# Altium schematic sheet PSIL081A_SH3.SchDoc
size 558 x 431 mm; Date: Not shown in title block; ApprovedBy: Not shown in title block; CheckedBy: Not shown in title block; Author: Not shown in title block; CompanyName: Not shown in title block; Engineer: Not shown in title block; Organization: Not shown in title block; Address1: Not shown in title block; Address2: Not shown in title block; Address3: Not shown in title block; Address4: Not shown in title block; DocumentNumber: 3; Revision: Use project parameter SCH_Rev; SheetNumber: 3; SheetTotal: 5; PageSetup: Record=PageOptions¦CenterHorizontal=True¦CenterVertical=True¦PrintScale=1.00¦XCorrection=1.00¦YCorrection=1.00¦PrintKind=0¦BorderSize=5000000¦LeftOffset=0¦BottomOffset=0¦Orientation=2¦PaperLength=1000¦PaperWidth=1000¦Scale=100¦PaperSource=15¦PrintQuality=600¦MediaType=1¦DitherType=10¦PaperKind=Letter¦PrintScaleMode=1
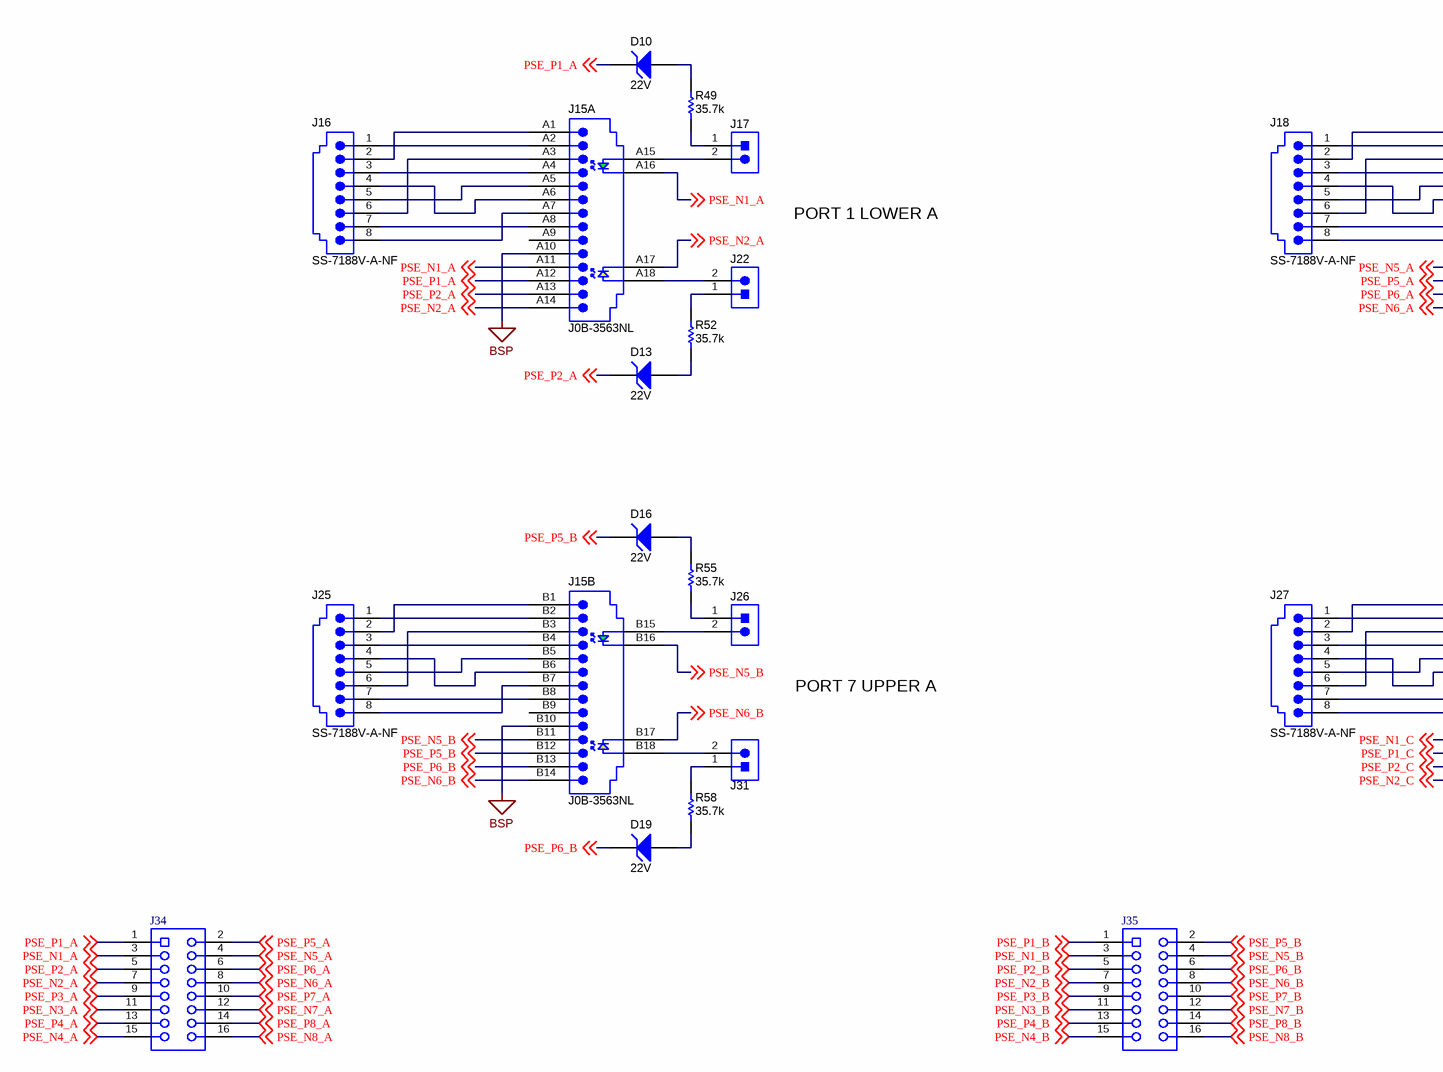
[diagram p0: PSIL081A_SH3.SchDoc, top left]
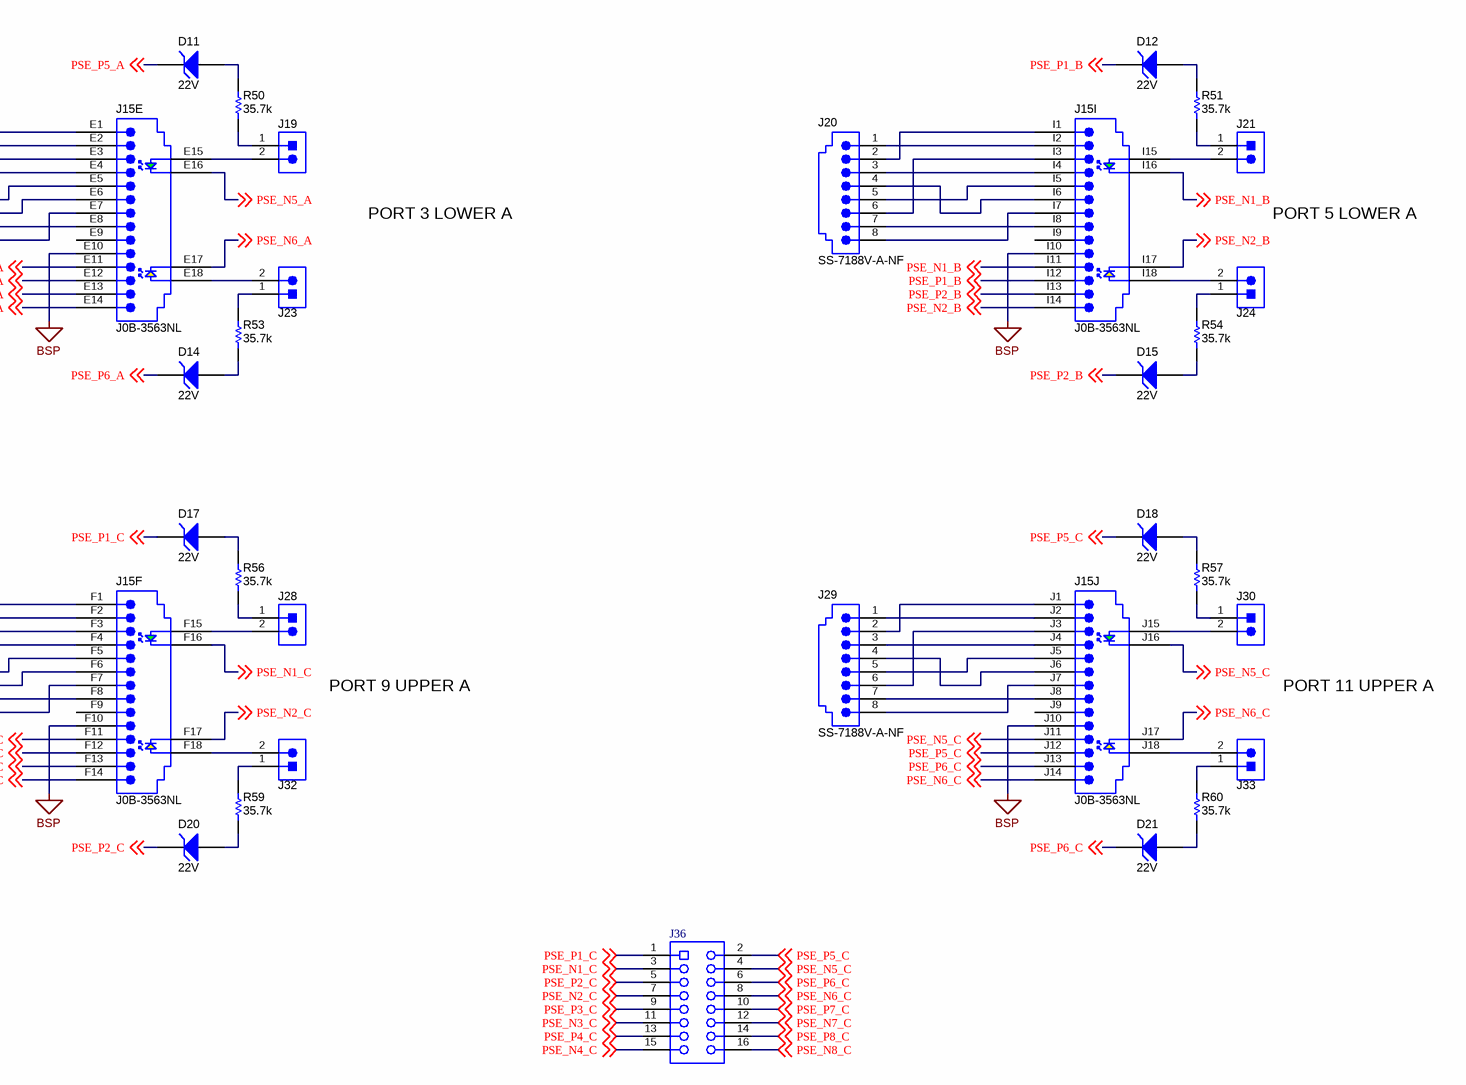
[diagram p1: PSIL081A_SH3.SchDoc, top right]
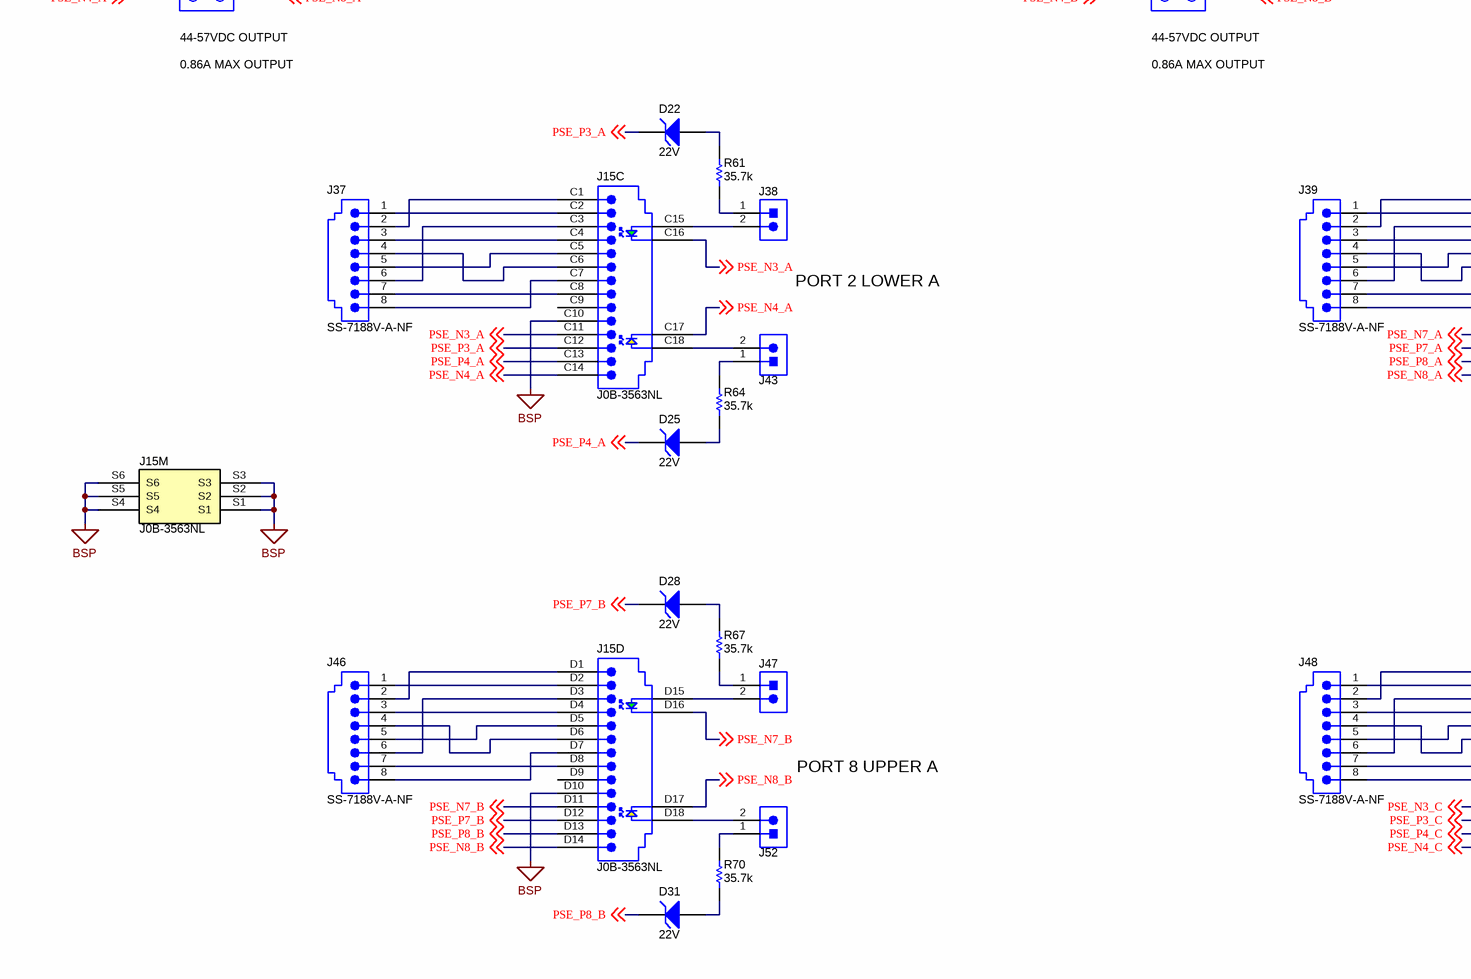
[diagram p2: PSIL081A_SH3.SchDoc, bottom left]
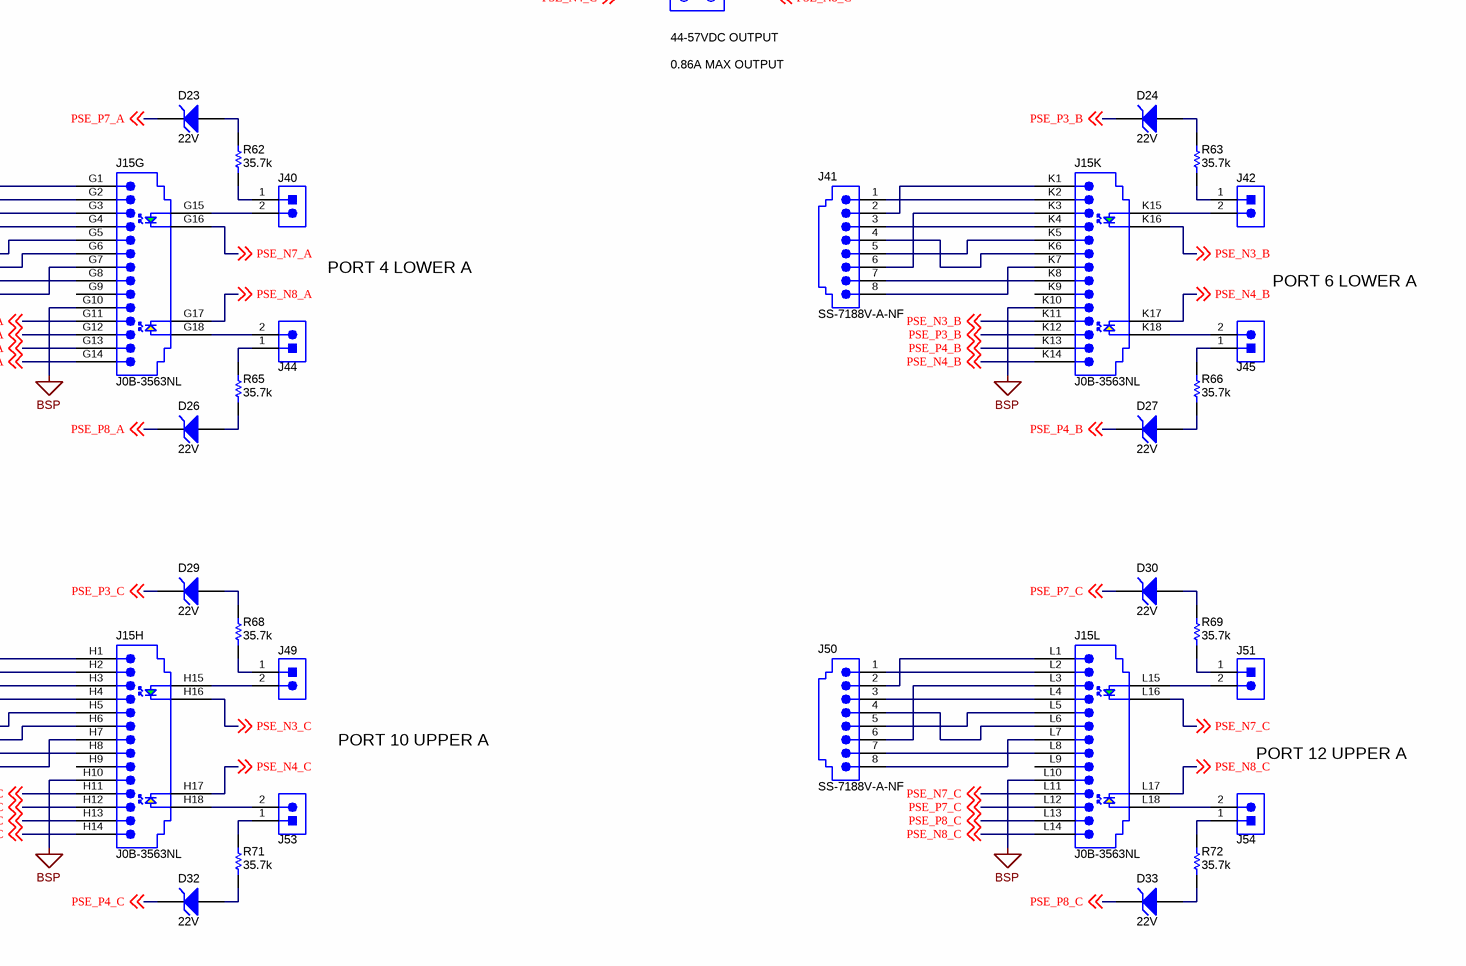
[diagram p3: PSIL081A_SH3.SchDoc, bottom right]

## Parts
D10  Vz_V: 22V  [SOD-123]  (hidden comment: MMSZ5251B-7-F)
D11  Vz_V: 22V  [SOD-123]  (hidden comment: MMSZ5251B-7-F)
D12  Vz_V: 22V  [SOD-123]  (hidden comment: MMSZ5251B-7-F)
D13  Vz_V: 22V  [SOD-123]  (hidden comment: MMSZ5251B-7-F)
D14  Vz_V: 22V  [SOD-123]  (hidden comment: MMSZ5251B-7-F)
D15  Vz_V: 22V  [SOD-123]  (hidden comment: MMSZ5251B-7-F)
D16  Vz_V: 22V  [SOD-123]  (hidden comment: MMSZ5251B-7-F)
D17  Vz_V: 22V  [SOD-123]  (hidden comment: MMSZ5251B-7-F)
D18  Vz_V: 22V  [SOD-123]  (hidden comment: MMSZ5251B-7-F)
D19  Vz_V: 22V  [SOD-123]  (hidden comment: MMSZ5251B-7-F)
D20  Vz_V: 22V  [SOD-123]  (hidden comment: MMSZ5251B-7-F)
D21  Vz_V: 22V  [SOD-123]  (hidden comment: MMSZ5251B-7-F)
D22  Vz_V: 22V  [SOD-123]  (hidden comment: MMSZ5251B-7-F)
D23  Vz_V: 22V  [SOD-123]  (hidden comment: MMSZ5251B-7-F)
D24  Vz_V: 22V  [SOD-123]  (hidden comment: MMSZ5251B-7-F)
D25  Vz_V: 22V  [SOD-123]  (hidden comment: MMSZ5251B-7-F)
D26  Vz_V: 22V  [SOD-123]  (hidden comment: MMSZ5251B-7-F)
D27  Vz_V: 22V  [SOD-123]  (hidden comment: MMSZ5251B-7-F)
D28  Vz_V: 22V  [SOD-123]  (hidden comment: MMSZ5251B-7-F)
D29  Vz_V: 22V  [SOD-123]  (hidden comment: MMSZ5251B-7-F)
D30  Vz_V: 22V  [SOD-123]  (hidden comment: MMSZ5251B-7-F)
D31  Vz_V: 22V  [SOD-123]  (hidden comment: MMSZ5251B-7-F)
D32  Vz_V: 22V  [SOD-123]  (hidden comment: MMSZ5251B-7-F)
D33  Vz_V: 22V  [SOD-123]  (hidden comment: MMSZ5251B-7-F)
J15  J0B-3563NL  [Pulse_J0B-3563NL]  (parts A,B,C,D,E,F,G,H,I,J,K,L,M of 13)
J16  SS-7188V-A-NF  [CONN_SS-7188V-A-NF]
J17  TSW-102-07-G-S  [TSW-102-07-G-S]  (value not drawn)
J18  SS-7188V-A-NF  [CONN_SS-7188V-A-NF]
J19  TSW-102-07-G-S  [TSW-102-07-G-S]  (value not drawn)
J20  SS-7188V-A-NF  [CONN_SS-7188V-A-NF]
J21  TSW-102-07-G-S  [TSW-102-07-G-S]  (value not drawn)
J22  TSW-102-07-G-S  [TSW-102-07-G-S]  (value not drawn)
J23  TSW-102-07-G-S  [TSW-102-07-G-S]  (value not drawn)
J24  TSW-102-07-G-S  [TSW-102-07-G-S]  (value not drawn)
J25  SS-7188V-A-NF  [CONN_SS-7188V-A-NF]
J26  TSW-102-07-G-S  [TSW-102-07-G-S]  (value not drawn)
J27  SS-7188V-A-NF  [CONN_SS-7188V-A-NF]
J28  TSW-102-07-G-S  [TSW-102-07-G-S]  (value not drawn)
J29  SS-7188V-A-NF  [CONN_SS-7188V-A-NF]
J30  TSW-102-07-G-S  [TSW-102-07-G-S]  (value not drawn)
J31  TSW-102-07-G-S  [TSW-102-07-G-S]  (value not drawn)
J32  TSW-102-07-G-S  [TSW-102-07-G-S]  (value not drawn)
J33  TSW-102-07-G-S  [TSW-102-07-G-S]  (value not drawn)
J34  SSW-108-21-G-D  [Samtec_SSW-108-01-x-D]  (value not drawn)
J35  SSW-108-21-G-D  [Samtec_SSW-108-01-x-D]  (value not drawn)
J36  SSW-108-21-G-D  [Samtec_SSW-108-01-x-D]  (value not drawn)
J37  SS-7188V-A-NF  [CONN_SS-7188V-A-NF]
J38  TSW-102-07-G-S  [TSW-102-07-G-S]  (value not drawn)
J39  SS-7188V-A-NF  [CONN_SS-7188V-A-NF]
J40  TSW-102-07-G-S  [TSW-102-07-G-S]  (value not drawn)
J41  SS-7188V-A-NF  [CONN_SS-7188V-A-NF]
J42  TSW-102-07-G-S  [TSW-102-07-G-S]  (value not drawn)
J43  TSW-102-07-G-S  [TSW-102-07-G-S]  (value not drawn)
J44  TSW-102-07-G-S  [TSW-102-07-G-S]  (value not drawn)
J45  TSW-102-07-G-S  [TSW-102-07-G-S]  (value not drawn)
J46  SS-7188V-A-NF  [CONN_SS-7188V-A-NF]
J47  TSW-102-07-G-S  [TSW-102-07-G-S]  (value not drawn)
J48  SS-7188V-A-NF  [CONN_SS-7188V-A-NF]
J49  TSW-102-07-G-S  [TSW-102-07-G-S]  (value not drawn)
J50  SS-7188V-A-NF  [CONN_SS-7188V-A-NF]
J51  TSW-102-07-G-S  [TSW-102-07-G-S]  (value not drawn)
J52  TSW-102-07-G-S  [TSW-102-07-G-S]  (value not drawn)
J53  TSW-102-07-G-S  [TSW-102-07-G-S]  (value not drawn)
J54  TSW-102-07-G-S  [TSW-102-07-G-S]  (value not drawn)
R49  ValueDisplayed: 35.7k  [0603]  (hidden comment: CRCW060335K7FKEA)
R50  ValueDisplayed: 35.7k  [0603]  (hidden comment: CRCW060335K7FKEA)
R51  ValueDisplayed: 35.7k  [0603]  (hidden comment: CRCW060335K7FKEA)
R52  ValueDisplayed: 35.7k  [0603]  (hidden comment: CRCW060335K7FKEA)
R53  ValueDisplayed: 35.7k  [0603]  (hidden comment: CRCW060335K7FKEA)
R54  ValueDisplayed: 35.7k  [0603]  (hidden comment: CRCW060335K7FKEA)
R55  ValueDisplayed: 35.7k  [0603]  (hidden comment: CRCW060335K7FKEA)
R56  ValueDisplayed: 35.7k  [0603]  (hidden comment: CRCW060335K7FKEA)
R57  ValueDisplayed: 35.7k  [0603]  (hidden comment: CRCW060335K7FKEA)
R58  ValueDisplayed: 35.7k  [0603]  (hidden comment: CRCW060335K7FKEA)
R59  ValueDisplayed: 35.7k  [0603]  (hidden comment: CRCW060335K7FKEA)
R60  ValueDisplayed: 35.7k  [0603]  (hidden comment: CRCW060335K7FKEA)
R61  ValueDisplayed: 35.7k  [0603]  (hidden comment: CRCW060335K7FKEA)
R62  ValueDisplayed: 35.7k  [0603]  (hidden comment: CRCW060335K7FKEA)
R63  ValueDisplayed: 35.7k  [0603]  (hidden comment: CRCW060335K7FKEA)
R64  ValueDisplayed: 35.7k  [0603]  (hidden comment: CRCW060335K7FKEA)
R65  ValueDisplayed: 35.7k  [0603]  (hidden comment: CRCW060335K7FKEA)
R66  ValueDisplayed: 35.7k  [0603]  (hidden comment: CRCW060335K7FKEA)
R67  ValueDisplayed: 35.7k  [0603]  (hidden comment: CRCW060335K7FKEA)
R68  ValueDisplayed: 35.7k  [0603]  (hidden comment: CRCW060335K7FKEA)
R69  ValueDisplayed: 35.7k  [0603]  (hidden comment: CRCW060335K7FKEA)
R70  ValueDisplayed: 35.7k  [0603]  (hidden comment: CRCW060335K7FKEA)
R71  ValueDisplayed: 35.7k  [0603]  (hidden comment: CRCW060335K7FKEA)
R72  ValueDisplayed: 35.7k  [0603]  (hidden comment: CRCW060335K7FKEA)

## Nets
BSP: J15.A10 J15.B10 J15.C10 J15.D10 J15.E10 J15.F10 J15.G10 J15.H10 J15.I10 J15.J10 J15.K10 J15.L10 J15.S1 J15.S2 J15.S3 J15.S4 J15.S5 J15.S6
PSE_N1_A: J15.A11 J15.A16 J34.3 ; off-sheet PSE_N1_A
PSE_N1_B: J15.I11 J15.I16 J35.3 ; off-sheet PSE_N1_B
PSE_N1_C: J15.F11 J15.F16 J36.3 ; off-sheet PSE_N1_C
PSE_N2_A: J15.A14 J15.A17 J34.7 ; off-sheet PSE_N2_A
PSE_N2_B: J15.I14 J15.I17 J35.7 ; off-sheet PSE_N2_B
PSE_N2_C: J15.F14 J15.F17 J36.7 ; off-sheet PSE_N2_C
PSE_N3_A: J15.C11 J15.C16 J34.11 ; off-sheet PSE_N3_A
PSE_N3_B: J15.K11 J15.K16 J35.11 ; off-sheet PSE_N3_B
PSE_N3_C: J15.H11 J15.H16 J36.11 ; off-sheet PSE_N3_C
PSE_N4_A: J15.C14 J15.C17 J34.15 ; off-sheet PSE_N4_A
PSE_N4_B: J15.K14 J15.K17 J35.15 ; off-sheet PSE_N4_B
PSE_N4_C: J15.H14 J15.H17 J36.15 ; off-sheet PSE_N4_C
PSE_N5_A: J15.E11 J15.E16 J34.4 ; off-sheet PSE_N5_A
PSE_N5_B: J15.B11 J15.B16 J35.4 ; off-sheet PSE_N5_B
PSE_N5_C: J15.J11 J15.J16 J36.4 ; off-sheet PSE_N5_C
PSE_N6_A: J15.E14 J15.E17 J34.8 ; off-sheet PSE_N6_A
PSE_N6_B: J15.B14 J15.B17 J35.8 ; off-sheet PSE_N6_B
PSE_N6_C: J15.J14 J15.J17 J36.8 ; off-sheet PSE_N6_C
PSE_N7_A: J15.G11 J15.G16 J34.12 ; off-sheet PSE_N7_A
PSE_N7_B: J15.D11 J15.D16 J35.12 ; off-sheet PSE_N7_B
PSE_N7_C: J15.L11 J15.L16 J36.12 ; off-sheet PSE_N7_C
PSE_N8_A: J15.G14 J15.G17 J34.16 ; off-sheet PSE_N8_A
PSE_N8_B: J15.D14 J15.D17 J35.16 ; off-sheet PSE_N8_B
PSE_N8_C: J15.L14 J15.L17 J36.16 ; off-sheet PSE_N8_C
PSE_P1_A: D10.1(K) J15.A12 J34.1 ; off-sheet PSE_P1_A
PSE_P1_B: D12.1(K) J15.I12 J35.1 ; off-sheet PSE_P1_B
PSE_P1_C: D17.1(K) J15.F12 J36.1 ; off-sheet PSE_P1_C
PSE_P2_A: D13.1(K) J15.A13 J34.5 ; off-sheet PSE_P2_A
PSE_P2_B: D15.1(K) J15.I13 J35.5 ; off-sheet PSE_P2_B
PSE_P2_C: D20.1(K) J15.F13 J36.5 ; off-sheet PSE_P2_C
PSE_P3_A: D22.1(K) J15.C12 J34.9 ; off-sheet PSE_P3_A
PSE_P3_B: D24.1(K) J15.K12 J35.9 ; off-sheet PSE_P3_B
PSE_P3_C: D29.1(K) J15.H12 J36.9 ; off-sheet PSE_P3_C
PSE_P4_A: D25.1(K) J15.C13 J34.13 ; off-sheet PSE_P4_A
PSE_P4_B: D27.1(K) J15.K13 J35.13 ; off-sheet PSE_P4_B
PSE_P4_C: D32.1(K) J15.H13 J36.13 ; off-sheet PSE_P4_C
PSE_P5_A: D11.1(K) J15.E12 J34.2 ; off-sheet PSE_P5_A
PSE_P5_B: D16.1(K) J15.B12 J35.2 ; off-sheet PSE_P5_B
PSE_P5_C: D18.1(K) J15.J12 J36.2 ; off-sheet PSE_P5_C
PSE_P6_A: D14.1(K) J15.E13 J34.6 ; off-sheet PSE_P6_A
PSE_P6_B: D19.1(K) J15.B13 J35.6 ; off-sheet PSE_P6_B
PSE_P6_C: D21.1(K) J15.J13 J36.6 ; off-sheet PSE_P6_C
PSE_P7_A: D23.1(K) J15.G12 J34.10 ; off-sheet PSE_P7_A
PSE_P7_B: D28.1(K) J15.D12 J35.10 ; off-sheet PSE_P7_B
PSE_P7_C: D30.1(K) J15.L12 J36.10 ; off-sheet PSE_P7_C
PSE_P8_A: D26.1(K) J15.G13 J34.14 ; off-sheet PSE_P8_A
PSE_P8_B: D31.1(K) J15.D13 J35.14 ; off-sheet PSE_P8_B
PSE_P8_C: D33.1(K) J15.L13 J36.14 ; off-sheet PSE_P8_C
NetD10_2: D10.2(A) R49.1
NetD11_2: D11.2(A) R50.1
NetD12_2: D12.2(A) R51.1
NetD13_2: D13.2(A) R52.2
NetD14_2: D14.2(A) R53.2
NetD15_2: D15.2(A) R54.2
NetD16_2: D16.2(A) R55.1
NetD17_2: D17.2(A) R56.1
NetD18_2: D18.2(A) R57.1
NetD19_2: D19.2(A) R58.2
NetD20_2: D20.2(A) R59.2
NetD21_2: D21.2(A) R60.2
NetD22_2: D22.2(A) R61.1
NetD23_2: D23.2(A) R62.1
NetD24_2: D24.2(A) R63.1
NetD25_2: D25.2(A) R64.2
NetD26_2: D26.2(A) R65.2
NetD27_2: D27.2(A) R66.2
NetD28_2: D28.2(A) R67.1
NetD29_2: D29.2(A) R68.1
NetD30_2: D30.2(A) R69.1
NetD31_2: D31.2(A) R70.2
NetD32_2: D32.2(A) R71.2
NetD33_2: D33.2(A) R72.2
NetJ15_A1: J15.A1 J16.2
NetJ15_A2: J15.A2 J16.1
NetJ15_A3: J15.A3 J16.6
NetJ15_A4: J15.A4 J16.3
NetJ15_A5: J15.A5 J16.5
NetJ15_A6: J15.A6 J16.4
NetJ15_A7: J15.A7 J16.8
NetJ15_A8: J15.A8 J16.7
NetJ15_A15: J15.A15 J17.2
NetJ15_A18: J15.A18 J22.2
NetJ15_B1: J15.B1 J25.2
NetJ15_B2: J15.B2 J25.1
NetJ15_B3: J15.B3 J25.6
NetJ15_B4: J15.B4 J25.3
NetJ15_B5: J15.B5 J25.5
NetJ15_B6: J15.B6 J25.4
NetJ15_B7: J15.B7 J25.8
NetJ15_B8: J15.B8 J25.7
NetJ15_B15: J15.B15 J26.2
NetJ15_B18: J15.B18 J31.2
NetJ15_C1: J15.C1 J37.2
NetJ15_C2: J15.C2 J37.1
NetJ15_C3: J15.C3 J37.6
NetJ15_C4: J15.C4 J37.3
NetJ15_C5: J15.C5 J37.5
NetJ15_C6: J15.C6 J37.4
NetJ15_C7: J15.C7 J37.8
NetJ15_C8: J15.C8 J37.7
NetJ15_C15: J15.C15 J38.2
NetJ15_C18: J15.C18 J43.2
NetJ15_D1: J15.D1 J46.2
NetJ15_D2: J15.D2 J46.1
NetJ15_D3: J15.D3 J46.6
NetJ15_D4: J15.D4 J46.3
NetJ15_D5: J15.D5 J46.5
NetJ15_D6: J15.D6 J46.4
NetJ15_D7: J15.D7 J46.8
NetJ15_D8: J15.D8 J46.7
NetJ15_D15: J15.D15 J47.2
NetJ15_D18: J15.D18 J52.2
NetJ15_E1: J15.E1 J18.2
NetJ15_E2: J15.E2 J18.1
NetJ15_E3: J15.E3 J18.6
NetJ15_E4: J15.E4 J18.3
NetJ15_E5: J15.E5 J18.5
NetJ15_E6: J15.E6 J18.4
NetJ15_E7: J15.E7 J18.8
NetJ15_E8: J15.E8 J18.7
NetJ15_E15: J15.E15 J19.2
NetJ15_E18: J15.E18 J23.2
NetJ15_F1: J15.F1 J27.2
NetJ15_F2: J15.F2 J27.1
NetJ15_F3: J15.F3 J27.6
NetJ15_F4: J15.F4 J27.3
NetJ15_F5: J15.F5 J27.5
NetJ15_F6: J15.F6 J27.4
NetJ15_F7: J15.F7 J27.8
NetJ15_F8: J15.F8 J27.7
NetJ15_F15: J15.F15 J28.2
NetJ15_F18: J15.F18 J32.2
NetJ15_G1: J15.G1 J39.2
NetJ15_G2: J15.G2 J39.1
NetJ15_G3: J15.G3 J39.6
NetJ15_G4: J15.G4 J39.3
NetJ15_G5: J15.G5 J39.5
NetJ15_G6: J15.G6 J39.4
NetJ15_G7: J15.G7 J39.8
NetJ15_G8: J15.G8 J39.7
NetJ15_G15: J15.G15 J40.2
NetJ15_G18: J15.G18 J44.2
NetJ15_H1: J15.H1 J48.2
NetJ15_H2: J15.H2 J48.1
NetJ15_H3: J15.H3 J48.6
NetJ15_H4: J15.H4 J48.3
NetJ15_H5: J15.H5 J48.5
NetJ15_H6: J15.H6 J48.4
NetJ15_H7: J15.H7 J48.8
NetJ15_H8: J15.H8 J48.7
NetJ15_H15: J15.H15 J49.2
NetJ15_H18: J15.H18 J53.2
NetJ15_I1: J15.I1 J20.2
NetJ15_I2: J15.I2 J20.1
NetJ15_I3: J15.I3 J20.6
NetJ15_I4: J15.I4 J20.3
NetJ15_I5: J15.I5 J20.5
NetJ15_I6: J15.I6 J20.4
NetJ15_I7: J15.I7 J20.8
NetJ15_I8: J15.I8 J20.7
NetJ15_I15: J15.I15 J21.2
NetJ15_I18: J15.I18 J24.2
NetJ15_J1: J15.J1 J29.2
NetJ15_J2: J15.J2 J29.1
NetJ15_J3: J15.J3 J29.6
NetJ15_J4: J15.J4 J29.3
NetJ15_J5: J15.J5 J29.5
NetJ15_J6: J15.J6 J29.4
NetJ15_J7: J15.J7 J29.8
NetJ15_J8: J15.J8 J29.7
NetJ15_J15: J15.J15 J30.2
NetJ15_J18: J15.J18 J33.2
NetJ15_K1: J15.K1 J41.2
NetJ15_K2: J15.K2 J41.1
NetJ15_K3: J15.K3 J41.6
NetJ15_K4: J15.K4 J41.3
NetJ15_K5: J15.K5 J41.5
NetJ15_K6: J15.K6 J41.4
NetJ15_K7: J15.K7 J41.8
NetJ15_K8: J15.K8 J41.7
NetJ15_K15: J15.K15 J42.2
NetJ15_K18: J15.K18 J45.2
NetJ15_L1: J15.L1 J50.2
NetJ15_L2: J15.L2 J50.1
NetJ15_L3: J15.L3 J50.6
NetJ15_L4: J15.L4 J50.3
NetJ15_L5: J15.L5 J50.5
NetJ15_L6: J15.L6 J50.4
NetJ15_L7: J15.L7 J50.8
NetJ15_L8: J15.L8 J50.7
NetJ15_L15: J15.L15 J51.2
NetJ15_L18: J15.L18 J54.2
NetJ17_1: J17.1 R49.2
NetJ19_1: J19.1 R50.2
NetJ21_1: J21.1 R51.2
NetJ22_1: J22.1 R52.1
NetJ23_1: J23.1 R53.1
NetJ24_1: J24.1 R54.1
NetJ26_1: J26.1 R55.2
NetJ28_1: J28.1 R56.2
NetJ30_1: J30.1 R57.2
NetJ31_1: J31.1 R58.1
NetJ32_1: J32.1 R59.1
NetJ33_1: J33.1 R60.1
NetJ38_1: J38.1 R61.2
NetJ40_1: J40.1 R62.2
NetJ42_1: J42.1 R63.2
NetJ43_1: J43.1 R64.1
NetJ44_1: J44.1 R65.1
NetJ45_1: J45.1 R66.1
NetJ47_1: J47.1 R67.2
NetJ49_1: J49.1 R68.2
NetJ51_1: J51.1 R69.2
NetJ52_1: J52.1 R70.1
NetJ53_1: J53.1 R71.1
NetJ54_1: J54.1 R72.1

Not connected (* = marked no-connect by the designer): J15 A9 B9 C9 D9 E9 F9 G9 H9 I9 J9 K9 L9

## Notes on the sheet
- PORT 1 LOWER A
- PORT 3 LOWER A
- PORT 5 LOWER A
- PORT 7 UPPER A
- PORT 9 UPPER A
- PORT 11 UPPER A
- (near J34) 44-57VDC OUTPUT
- (near J35) 44-57VDC OUTPUT
- 0.86A MAX OUTPUT
- (near J36) 44-57VDC OUTPUT
- PORT 2 LOWER A
- PORT 4 LOWER A
- PORT 6 LOWER A
- PORT 8 UPPER A
- PORT 10 UPPER A
- PORT 12 UPPER A

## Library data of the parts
D10-D33 = CMP-0005757-2: Diode, Zener, 22 V, 500 mW, SOD-123; Manufacturer: Diodes Inc.; Power_W: 500mW; SizeAreaWB_mm2: 13.095; Value1: 0.5W; RJA_CperW: 350; U/M: EA; Value: 22V; SizeZ_mm: 1.35; SizeX_mm: 3.85; SizeY_mm: 1.7; SizeArea_mm2: 6.545; AEC Category: Q101
J15 = CMP-0081711-4: 12 Port RJ45, R/A, TH; Manufacturer: Pulse Engineering; Gender: Female; ContactFinish: Gold
J16 J18 J20 J25 J27 J29 J37 J39 J41 J46 J48 J50 = CMP-0055855-1: RJ45, Vertical, TH; Manufacturer: Stewart Connector; CT: TRUE; Green_REACh: Incomplete; CNHeader: FALSE; Green_Lifecycle: Not Set
J17 J19 J21-J24 J26 J28 J30-J33 J38 J40 J42-J45 J47 J49 J51-J54 = CMP-0075405-2: Header, 100mil, 2x1, Gold, TH; Manufacturer: Samtec; Pitch_mm: 2.54; Cert_VDE: N; Gender: Male; Cert_CSA: Y; Voltage_V: 550V; Green_REACh: Passed; Current_A: 6.3A; Green_Lifecycle: Active; Row_Count: 1
J34-J36 = CMP-0750077-1: Receptacle, 2.54mm, 8x2, Gold, TH; Manufacturer: Samtec; Pitch_mm: 2.54; Gender: Female; Current_A: 4.7A; Cert_UL: Y; Row_Count: 2; Voltage_V: 655V
R49-R72 = CMP-0022352-4: RES, 35.7 k, 1%, 0.1 W, AEC-Q200 Grade 0, 0603; Manufacturer: Vishay-Dale; Power_W: 100mW; TempCo: 100 ppm/C; Value_Code: 35k7; Value: 35.7k; EIA_Code: E96; SizeX_mm: 1.6; SizeY_mm: 0.8; SizeZ_mm: 1; Value2: 0.1W; SizeArea_mm2: 1.28; AEC Qualified: Y; VDC_V: 75V; AEC Category: Q200; AEC Grade: 0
